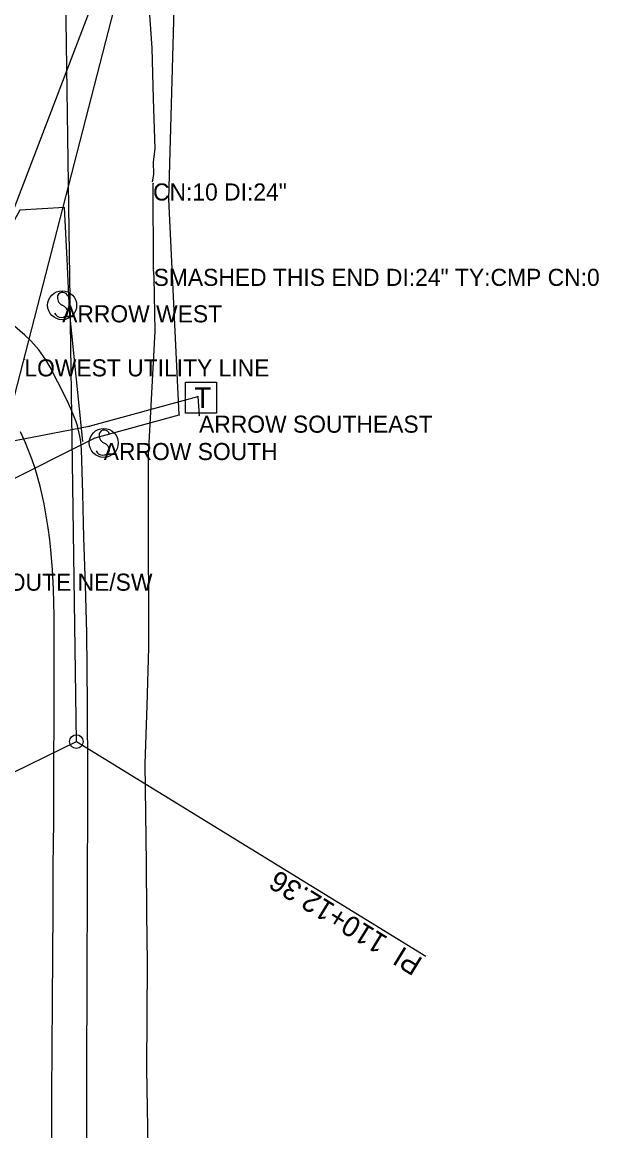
# Model space of a CAD drawing. Extents: x 1674300 to 1677920, y 225056 to 231852.
# Drawn here: x 1677374.1 to 1677542.8, y 227976.6 to 228300.9 of the extents above; entities that cross this region are included whole.
import ezdxf

# ---------------------------------------------------------------- set-up
doc = ezdxf.new("R2010")
doc.units = 0
for name, color, linetype in [('R_Horz Alg', 7, 'Continuous'), ('R_Horz Alg Annot', 7, 'Continuous'), ('S_DITCHLINE', 7, 'Continuous'), ('S_DRG_PT_SYM', 7, 'Continuous'), ('S_EDGE_PAVEMENT', 7, 'Continuous'), ('S_ELECTRIC_UTILITIES', 7, 'Continuous'), ('S_ELECTRIC_UTILITIES_ANNOT', 7, 'Continuous'), ('S_EXIST_ROW', 7, 'Continuous'), ('S_FIBER_OPTIC_CABLE', 7, 'Continuous'), ('S_FIBER_OPTIC_CABLE_ANNOT', 7, 'Continuous'), ('S_GRAVEL_ROAD', 7, 'Continuous'), ('S_MSC_PT_SYM', 7, 'Continuous'), ('S_PAVEMENT_CROWN', 7, 'Continuous'), ('S_SIDE_DRAIN', 7, 'Continuous'), ('S_SIDE_DRAIN_ANNOT', 7, 'Continuous'), ('S_SIGN', 7, 'Continuous'), ('S_SIGN_ANNOT', 7, 'Continuous'), ('S_TELEPHONE_UTILITIES', 7, 'Continuous'), ('S_UTILITY_POLE_ANNOT', 7, 'Continuous'), ('S_UTL_PT_SYM', 7, 'Continuous')]:
    doc.layers.add(name, color=color, linetype=linetype)

msp = doc.modelspace()

# ---------------------------------------------------------------- linework, layer by layer
at = {"layer": 'R_Horz Alg'}
msp.add_arc((1675928.16, 228988.54), 1449, 296.0624, 0.80558, dxfattribs=at)
at = {"layer": 'R_Horz Alg Annot'}
for p, q in [((1677389.93, 228090.45), (1677377.01, 229008.91)), ((1676564.78, 227686.88), (1677389.93, 228090.45))]:
    msp.add_line(p, q, dxfattribs=at)
msp.add_lwpolyline([(1677389.93, 228090.45), (1677492.17, 228027.63)], dxfattribs=at)
msp.add_circle((1677389.93, 228090.45), 2, dxfattribs=at)
at = {"layer": 'S_DITCHLINE'}
for points in [[(1677412.24, 228254.17), (1677412.6, 228256.39), (1677412.47, 228260.11), (1677413, 228263.83), (1677412.54, 228278.59), (1677412.08, 228293.34), (1677411.18, 228307.32)], [(1677411.34, 227948.81), (1677410.93, 227971.75), (1677410.52, 227994.7), (1677410.65, 228010.19), (1677410.77, 228025.67), (1677410.6, 228040.23), (1677410.43, 228054.8), (1677410.25, 228069.36), (1677410.08, 228083.92), (1677410.62, 228100.96), (1677411.16, 228118), (1677411.12, 228132.07), (1677411.08, 228146.13), (1677411.04, 228160.19), (1677411, 228174.26), (1677412.02, 228192.39), (1677413.03, 228210.53), (1677412.69, 228226.29), (1677412.54, 228228.6)]]:
    msp.add_lwpolyline(points, dxfattribs=at)
at = {"layer": 'S_DRG_PT_SYM'}
for points in [[(1677412.36, 228253.75), (1677412.36, 228253.8), (1677412.36, 228253.75), (1677412.31, 228253.75), (1677412.36, 228253.75), (1677412.36, 228253.7), (1677412.36, 228253.75), (1677412.41, 228253.75)], [(1677412.53, 228228.77), (1677412.53, 228228.82), (1677412.53, 228228.77), (1677412.48, 228228.77), (1677412.53, 228228.77), (1677412.53, 228228.72), (1677412.53, 228228.77), (1677412.58, 228228.77)]]:
    msp.add_lwpolyline(points, dxfattribs=at)
at = {"layer": 'S_EDGE_PAVEMENT'}
msp.add_lwpolyline([(1677392.99, 227973.14), (1677393.01, 227986.86), (1677393.04, 228000.57), (1677393.07, 228014.29), (1677393.1, 228028), (1677393.16, 228041.08), (1677393.22, 228054.15), (1677393.28, 228067.22), (1677393.33, 228080.3), (1677393.16, 228101.3), (1677392.99, 228122.29), (1677392.57, 228136.22), (1677392.15, 228150.14), (1677391.79, 228163.04), (1677391.42, 228175.94), (1677391.24, 228178.28), (1677390.99, 228179.8), (1677390.25, 228182.79), (1677389.77, 228184.26), (1677388.64, 228187.15), (1677387.33, 228190), (1677384.48, 228195.62), (1677382.22, 228199.98), (1677381.02, 228202.09), (1677378.99, 228205.06), (1677376.64, 228207.74), (1677374.9, 228209.39), (1677371.13, 228212.53)], dxfattribs=at)
at = {"layer": 'S_ELECTRIC_UTILITIES'}
msp.add_line((1677343.16, 228080.48), (1677425.49, 228399.8), dxfattribs=at)
at = {"layer": 'S_EXIST_ROW'}
msp.add_line((1677344.31, 228175.41), (1677424.97, 228385.14), dxfattribs=at)
at = {"layer": 'S_FIBER_OPTIC_CABLE'}
for p, q in [((1677416.97, 228249.14), (1677419.05, 228321.79)), ((1677420.05, 228186.02), (1677416.97, 228249.14)), ((1677393.7, 228182.74), (1677425.52, 228191.41)), ((1677425.52, 228191.41), (1677425.83, 228185.81)), ((1677395.47, 228179.35), (1677420.05, 228186.02)), ((1677354.08, 228175.16), (1677393.7, 228182.74)), ((1677362.65, 228162.87), (1677395.47, 228179.35))]:
    msp.add_line(p, q, dxfattribs=at)
at = {"layer": 'S_GRAVEL_ROAD'}
msp.add_lwpolyline([(1677391.86, 228178.22), (1677389.92, 228197.38), (1677387.97, 228216.53), (1677387.22, 228231.6), (1677386.46, 228246.68), (1677373.41, 228245.91), (1677367.22, 228234.89), (1677361.37, 228232.62), (1677351.91, 228228.25)], dxfattribs=at)
at = {"layer": 'S_MSC_PT_SYM'}
msp.add_lwpolyline([(1677374.72, 228202.29), (1677374.72, 228202.34), (1677374.72, 228202.29), (1677374.67, 228202.29), (1677374.72, 228202.29), (1677374.72, 228202.24), (1677374.72, 228202.29), (1677374.77, 228202.29)], dxfattribs=at)
at = {"layer": 'S_PAVEMENT_CROWN'}
msp.add_lwpolyline([(1677382.74, 227973.42), (1677382.8, 227987.07), (1677382.87, 228000.72), (1677382.94, 228014.37), (1677383, 228028.03), (1677383.1, 228041.01), (1677383.19, 228053.99), (1677383.29, 228066.97), (1677383.38, 228079.96), (1677383.41, 228101.62), (1677383.44, 228123.28), (1677383.42, 228127.21), (1677383.25, 228135), (1677382.95, 228140.8), (1677382.48, 228146.58), (1677382.17, 228149.46), (1677381.72, 228152.98), (1677380.52, 228159.98), (1677379.34, 228165.18), (1677377.86, 228170.3), (1677377.01, 228172.83), (1677375.04, 228177.84), (1677373.54, 228181.1)], dxfattribs=at)
at = {"layer": 'S_SIDE_DRAIN'}
msp.add_line((1677412.53, 228228.77), (1677412.36, 228253.75), dxfattribs=at)
at = {"layer": 'S_SIGN'}
for centre in [(1677385.77, 228218.09), (1677397.95, 228177.81)]:
    msp.add_circle(centre, 4.24, dxfattribs=at)
for centre, radius, start, end in [((1677385.9, 228220.25), 1.62, 16.5258, 156.8957), ((1677386.94, 228220.35), 2.55, 167.1196, 241.9813), ((1677385.51, 228216.69), 2.17, 204.641, 335.359), ((1677385.07, 228215.81), 2.38, 358.6529, 73.7063), ((1677399.12, 228180.06), 2.55, 167.1196, 241.9813), ((1677398.08, 228179.96), 1.62, 16.5258, 156.8957), ((1677397.25, 228175.52), 2.38, 358.6529, 73.7063), ((1677397.69, 228176.41), 2.17, 204.641, 335.359)]:
    msp.add_arc(centre, radius, start, end, dxfattribs=at)
at = {"layer": 'S_TELEPHONE_UTILITIES'}
msp.add_lwpolyline([(1677421.91, 228186.56), (1677421.91, 228195.56), (1677430.91, 228195.56), (1677430.91, 228186.56)], close=True, dxfattribs=at)
at = {"layer": 'S_UTL_PT_SYM'}
for points in [[(1677416.97, 228249.14), (1677416.97, 228249.19), (1677416.97, 228249.14), (1677416.92, 228249.14), (1677416.97, 228249.14), (1677416.97, 228249.09), (1677416.97, 228249.14), (1677417.02, 228249.14)], [(1677374.72, 228202.29), (1677374.72, 228202.34), (1677374.72, 228202.29), (1677374.67, 228202.29), (1677374.72, 228202.29), (1677374.72, 228202.24), (1677374.72, 228202.29), (1677374.77, 228202.29)], [(1677425.52, 228191.41), (1677425.52, 228191.46), (1677425.52, 228191.41), (1677425.47, 228191.41), (1677425.52, 228191.41), (1677425.52, 228191.36), (1677425.52, 228191.41), (1677425.57, 228191.41)], [(1677420.05, 228186.02), (1677420.05, 228186.07), (1677420.05, 228186.02), (1677420, 228186.02), (1677420.05, 228186.02), (1677420.05, 228185.97), (1677420.05, 228186.02), (1677420.1, 228186.02)], [(1677393.7, 228182.74), (1677393.7, 228182.79), (1677393.7, 228182.74), (1677393.65, 228182.74), (1677393.7, 228182.74), (1677393.7, 228182.69), (1677393.7, 228182.74), (1677393.75, 228182.74)], [(1677425.83, 228185.81), (1677425.83, 228185.86), (1677425.83, 228185.81), (1677425.78, 228185.81), (1677425.83, 228185.81), (1677425.83, 228185.76), (1677425.83, 228185.81), (1677425.88, 228185.81)], [(1677395.47, 228179.35), (1677395.47, 228179.4), (1677395.47, 228179.35), (1677395.42, 228179.35), (1677395.47, 228179.35), (1677395.47, 228179.3), (1677395.47, 228179.35), (1677395.52, 228179.35)]]:
    msp.add_lwpolyline(points, dxfattribs=at)

# ---------------------------------------------------------------- texts
at = {"layer": 'R_Horz Alg Annot'}
msp.add_text('PI  110+12.36', height=6, rotation=148.434, dxfattribs=at).set_placement((1677491.65, 228026.78))
at = {"layer": 'S_ELECTRIC_UTILITIES_ANNOT'}
msp.add_text('LOWEST UTILITY LINE', height=5, rotation=360, dxfattribs=at).set_placement((1677374.72, 228197.29))
at = {"layer": 'S_FIBER_OPTIC_CABLE_ANNOT'}
msp.add_text('ARROW SOUTHEAST', height=5, rotation=360, dxfattribs=at).set_placement((1677425.83, 228180.81))
at = {"layer": 'S_SIDE_DRAIN_ANNOT'}
for s, p in [('CN:10 DI:24"', (1677412.36, 228248.75)), ('SMASHED THIS END DI:24" TY:CMP CN:0', (1677412.53, 228223.77))]:
    msp.add_text(s, height=5, rotation=360, dxfattribs=at).set_placement(p)
at = {"layer": 'S_SIGN_ANNOT'}
for s, p in [('ARROW WEST', (1677385.77, 228213.09)), ('ARROW SOUTH', (1677397.95, 228172.81))]:
    msp.add_text(s, height=5, rotation=360, dxfattribs=at).set_placement(p)
at = {"layer": 'S_TELEPHONE_UTILITIES'}
msp.add_text('T', height=6, rotation=360, dxfattribs=at).set_placement((1677424.47, 228188.06))
at = {"layer": 'S_UTILITY_POLE_ANNOT'}
msp.add_text('CABLE ROUTE NE/SW', height=5, rotation=360, dxfattribs=at).set_placement((1677341.24, 228134.58))

doc.saveas('drawing.dxf')
